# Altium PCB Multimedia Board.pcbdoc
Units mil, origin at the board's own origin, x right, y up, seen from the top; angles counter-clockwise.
Board outline 8820.47 x 865.35 mil, 4 copper layers (Top Layer, InternalPlane1, InternalPlane2, Bottom Layer); 37 components, 38 nets, 94 pads, 30 vias.
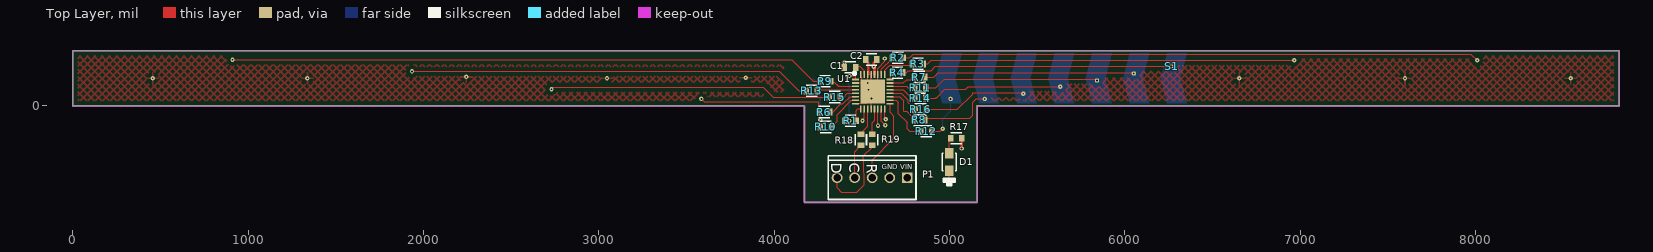
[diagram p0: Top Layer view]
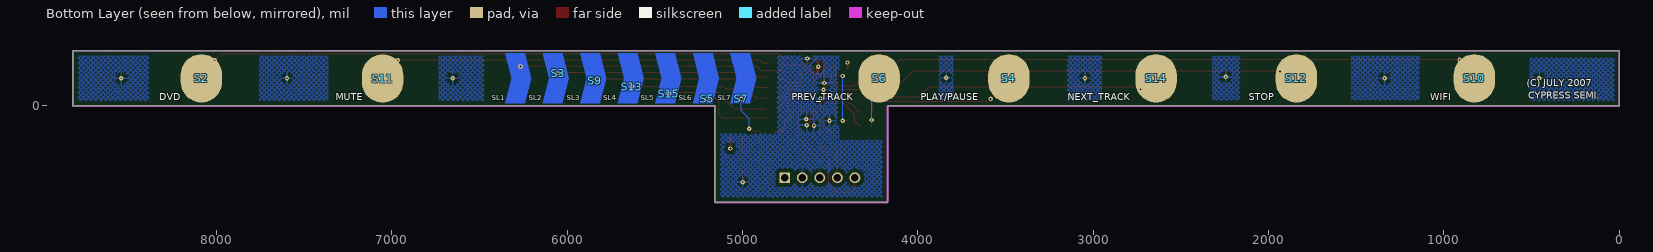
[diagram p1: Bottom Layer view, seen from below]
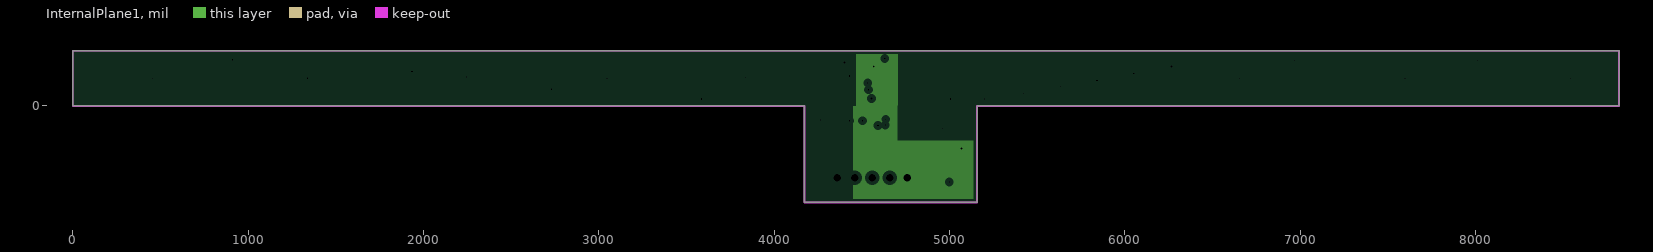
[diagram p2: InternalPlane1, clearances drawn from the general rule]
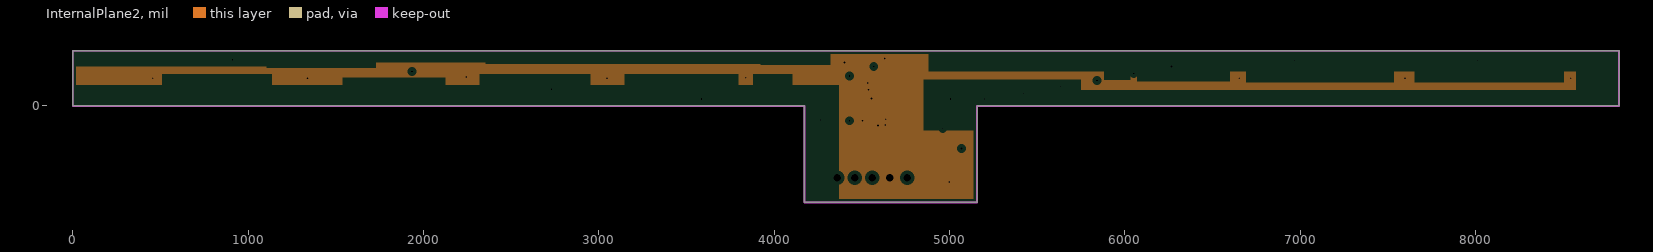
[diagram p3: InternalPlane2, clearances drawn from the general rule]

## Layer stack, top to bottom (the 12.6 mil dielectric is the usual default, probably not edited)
Top Layer: signal copper 1.4
Dielectric: prepreg 12.6, FR-4, Dk 4.8
InternalPlane1: plane copper 1.4, net VCC
Dielectric: prepreg 12.6, FR-4, Dk 4.8
InternalPlane2: plane copper 1.4, net GND
Dielectric: core 12.6, FR-4, Dk 4.8
Bottom Layer: signal copper 1.4

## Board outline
0,0 4172.05,0.39 4172.05,-550.39 5157.87,-550.39 5157.87,0.39 8820.47,0.39 8820.47,314.57 0,314.96

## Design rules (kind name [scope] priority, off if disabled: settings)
Clearance Clearance_1 [All vs InPoly] p1: gap=20
Clearance [All] p2: gap=7
ComponentClearance [All] p1 off: gap=10 collisioncheckmode=3 verticalgap=10
DiffPairsRouting [All] p1 off: maxlimit=10 minlimit=10 mostfreqgap=10 maxuncoupledlength=500
FanoutControl Fanout_BGA [IsBGA] p1 off: bgadir=Out bgaviamode=Centered fanoutstyle=Auto fanoutdirection=Alternating viagrid=1 // Fanout_BGA (Default Rule)
FanoutControl Fanout_LCC [IsLCC] p2 off: bgadir=Out bgaviamode=Centered fanoutstyle=Auto fanoutdirection=Alternating viagrid=1 // Fanout_LCC (Default Rule)
FanoutControl Fanout_SOIC [IsSOIC] p3 off: bgadir=Out bgaviamode=Centered fanoutstyle=Auto fanoutdirection=Alternating viagrid=1 // Fanout_SOIC (Default Rule)
FanoutControl Fanout_Small [(CompPinCount < 5)] p4 off: bgadir=Out bgaviamode=Centered fanoutstyle=Auto fanoutdirection=OutThenIn viagrid=1 // Fanout_Small (Default Rule)
FanoutControl Fanout_Default [All] p5 off: bgadir=Out bgaviamode=Centered fanoutstyle=Auto fanoutdirection=Alternating viagrid=1 // Fanout_Default (Default Rule)
HoleSize [All] p1: absolutevalues=TRUE maxlimit=150 minlimit=10 maxpercent=80.000 minpercent=20.000
MatchedLengths [InNetClass('ITO signals')] p1: tolerance=1000 amplitude=200 gap=20 style=Round
PlaneClearance [All] p1: clearance=20
PlaneConnect [All] p1: planeconnectstyle=Relief reliefexpansion=20 reliefentries=4 reliefconductorwidth=10 reliefairgap=10
PolygonConnect [All] p1: connectstyle=Relief reliefconductorwidth=10 reliefentries=4 polygonreliefangle="90 Angle"
RoutingTopology [All] p1 off: topology=Shortest
RoutingVias [All] p1: holewidth=10 width=25 viastyle="Through Hole" minholewidth=10 minwidth=25 maxholewidth=10 maxwidth=25
SMDNeckDown [All] p1 off: percent=80.000
SMDToPlane SMDToPlane_1 [InNet('VDD')] p1 off: distance=300000
SMDToPlane [InNet('GND')] p2 off: distance=300000
SolderMaskExpansion [All] p1: expansion=3
TestPointUsage [All] p1: valid=0 allowmultiple=FALSE
Testpoint [All] p1: side=15 testpointundercomponent=TRUE minsize=40 maxsize=100 preferedsize=60 minholesize=0 maxholesize=40 preferedholesize=32 testpointgrid=1 style=1023 order=0123456789
Width [All] p1: maxlimit=100 minlimit=7 preferedwidth=7 minimp=50.000000 maximp=50.000000 favimp=50.000000
8 further rules are at their usual default settings.

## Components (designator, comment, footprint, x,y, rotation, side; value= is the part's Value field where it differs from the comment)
C1 "0.1uF, 0603" 0603 4464.52,220 r180 top
C2 "0.1uF, 0603" 0603 4586.76,264.94 r180 top
D1 "LED" 0805LED 4999.52,-269.29 r270 top
P1 "ISSP_CON" ISPCON 4759.52,-409.29 r180 top
R1 "1K" 0603 4404.52,-84.29 r0 top
R2 "560 OHM" 0603 4736.76,274.94 r180 top
R3 "560 OHM" 0603 4851.76,239.94 r180 top
R4 "560 OHM" 0603 4734.75,189.94 r180 top
R6 "560 OHM" 0603 4316.76,-35.06 r180 top
R7 "560 OHM" 0603 4859.75,164.94 r180 top
R8 "560 OHM" 0603 4797.01,-80 r0 top
R9 "560 OHM" 0603 4259.52,140.71 r0 top
R10 "560 OHM" 0603 4326.76,-120.06 r180 top
R11 "560 OHM" 0603 4864.76,104.02 r180 top
R12 "560 OHM" 0603 4836.76,-145.06 r0 top
R13 "560 OHM" 0603 4184.52,85.71 r0 top
R14 "560 OHM" 0603 4864.75,44.94 r180 top
R15 "560 OHM" 0603 4314.52,50.71 r0 top
R16 "560 OHM" 0603 4866.76,-20.06 r180 top
R17 "330 OHM, 0603" 0603 5069.52,-184.29 r180 top
R18 "300 OHM" 0603 4495,-162.01 r270 top
R19 "300 OHM" 0603 4560,-162.01 r270 top
S1 "SL1" CAPSENSE_PAD 6266.85,225.04 r180 top
S2 "DVD" "BUTTON 9mm no silk"#1 7999.52,112.71 r180 top
S3 "SL2" CAPSENSE_PAD 6051.68,185.02 r0 bottom
S4 "PLAY/PAUSE" "BUTTON 9mm no silk"#2 3902.52,92.71 r180 top
S5 "SL6" CAPSENSE_PAD 5201.61,39.96 r0 bottom
S6 "PREV_TRACK" "BUTTON 9mm no silk"#3 4495.52,147.71 r180 top
S7 "SL7" CAPSENSE_PAD 5006.69,40.04 r0 bottom
S9 "SL3" CAPSENSE_PAD 5841.68,145.02 r0 bottom
S10 "WIFI" "BUTTON 9mm no silk"#4 2070.52,87.71 r180 top
S11 "MUTE" "BUTTON 9mm no silk"#5 7252.27,105.94 r180 top
S12 "STOP" "BUTTON 9mm no silk"#6 2556.52,92.71 r180 top
S13 "SL4" CAPSENSE_PAD 5631.69,110.04 r0 bottom
S14 "NEXT_TRACK" "BUTTON 9mm no silk"#7 3124.51,72.7 r180 top
S15 "SL5" CAPSENSE_PAD 5421.69,70.04 r0 bottom
U1 "CY8C21434-32PIN" 32-MLF 4464.52,150.71 r0 top

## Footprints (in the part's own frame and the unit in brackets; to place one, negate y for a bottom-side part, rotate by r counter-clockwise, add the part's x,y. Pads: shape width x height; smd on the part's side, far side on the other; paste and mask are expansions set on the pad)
32-MLF [mm]
  rect 3.5x3.5 smd: 0(2.5,-1.75)
  rect 1x0.23 smd: 1(0,0) 2(0,-0.5) 3(0,-1) 4(0,-1.5) 5(0,-2) 6(0,-2.5) 7(0,-3) 8(0,-3.5) 17(5,-3.5) 18(5,-3) 19(5,-2.5) 20(5,-2) 21(5,-1.5) 22(5,-1) 23(5,-0.5) 24(5,0)
  rect 0.23x1 smd: 9(0.75,-4.25) 10(1.25,-4.25) 11(1.75,-4.25) 12(2.25,-4.25) 13(2.75,-4.25) 14(3.25,-4.25) 15(3.75,-4.25) 16(4.25,-4.25) 25(4.25,0.75) 26(3.75,0.75) 27(3.25,0.75) 28(2.75,0.75) 29(2.25,0.75) 30(1.75,0.75) 31(1.25,0.75) 32(0.75,0.75)
  silkscreen extent -0.35,0.7 0.05,1.1
0603 [mm]
  rect 0.8x1 smd: 1(0,0) 2(1.6,0)
  silkscreen extent 0,-0.81 1.58,0.81
0805LED [mil]
  rect 60x50 smd: 1(0,0) 2(100,0)
  silkscreen extent 0,-40 187,40
"BUTTON 9mm no silk"#1 [mm]
  oval 6x7 smd far side: 1(-2.216,-1.137)
"BUTTON 9mm no silk"#2 [mm]
  oval 6x7 smd far side: 1(10.687,-1.645)
"BUTTON 9mm no silk"#3 [mm]
  oval 6x7 smd far side: 1(6.953,-0.248)
"BUTTON 9mm no silk"#4 [mm]
  oval 6x7 smd far side: 1(31.591,-1.772)
"BUTTON 9mm no silk"#5 [mm]
  oval 6x7 smd far side: 1(5.074,-1.264)
"BUTTON 9mm no silk"#6 [mm]
  oval 6x7 smd far side: 1(18.155,-1.645)
"BUTTON 9mm no silk"#7 [mm]
  oval 6x7 smd far side: 1(12.263,-2.152)
CAPSENSE_PAD [mil] "CAPSENSE_PAD"
  round 25 hole 10: 1(0.08,0.08)
ISPCON [mil]
  rect 62x62 hole 42: 1(0,0)
  round 62 hole 42: 2(100,0) 3(200,0) 4(300,0) 5(400,0)
  silkscreen extent -50,-125 450,125

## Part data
C1 C2: library part CAP, "Capacitor"
D1: "BLUE"
P1: "PSoC Programming Connector"
R1 R2 R3 R4 R6 R7 R8 R9 R10 R11 R12 R13 R14 R15 R16 R17 R18 R19: library part RES, "RESISTOR"
S1 S2 S3 S4 S5 S6 S7 S9 S10 S11 S12 S13 S14 S15: library part "CAPSENSE BUTTON"
U1: library part CY8C21434-24LFXI, "32  MLF"

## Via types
v1: diameter 25, hole 10, Top Layer to Bottom Layer, tented both sides, 16 vias
v2: diameter 25, hole 10, Top Layer to Bottom Layer, 14 vias

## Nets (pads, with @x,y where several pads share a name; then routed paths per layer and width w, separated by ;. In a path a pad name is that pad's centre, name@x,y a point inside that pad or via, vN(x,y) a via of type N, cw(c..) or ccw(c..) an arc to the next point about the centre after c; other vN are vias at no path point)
GND: C1.2 C2.2 D1.2 P1.2 U1.0 U1.2 U1.8 U1.10 U1.12 U1.14 U1.15 U1.16 U1.27 U1.29 U1.30 U1.32 | length 1127.4
  Top Layer w7: U1.8 4479.02,12.91 4481.82,15.71 4529.52,15.71 v2(4555.52,41.71) U1.12 ; U1.2 4534.21,131.02 v2(4534.52,130.71) ; U1.2@4479.41,131.02 U1.2@4479.72,130.71 ; U1.32 4494.05,165.74 4498.7,161.08 4498.7,131.52 v2(4538.52,91.71) ; v2(4504.52,-84.29) 4513.73,-75.08 U1.10 ; U1.30@4534.52,179.13 v2(4534.52,130.71) ; U1.30@4535.62,180.24 U1.29 4553.1,137.13 4546.68,130.71 v2(4534.52,130.71) ; U1.30@4536.53,191.14 4541.53,186.14 ; U1.0@4590.42,130.71 4592.47,132.76 4592.47,216.25 4594.44,216.25 4631.69,253.5 v2(4631.69,270.83) ; v2(4592.47,-112.24) U1.14 ; U1.15 4612.16,-86.93 v2(4634.52,-109.29) ; U1.16 4631.84,-71.61 v2(4636.52,-76.29) ; v2(4999.52,-434.29) D1.2
  Top Layer w10: C1.2@4401.53,210.71 v2(4401.53,247.72) ; 4541.53,186.14 4547.2,186.14
  Top Layer w15: U1.30@4536.53,191.14 C2.2@4536.53,245.71
  other v1: 456.69,157.48 1338.58,157.48 3047.24,157.48 6653.54,157.48 7598.43,157.48 8543.31,157.48 3838.58,161.42 2244.09,165.35
NetC1_1: C1.1 R1.1 U1.1 U1.31 | length 461.7
  Top Layer w7: R1.1 v2(4429.52,-84.29) ; v2(4429.52,170.71) 4464.52,170.71 ; U1.1 4464.52,210.71 4479.52,225.71 4489.52,225.71 4513.73,201.5 U1.31
  Bottom Layer w7: v2(4429.52,-84.29) v2(4429.52,170.71)
NetD1_1: D1.1 R17.2 | length 87.9
  Top Layer w7: D1.1 4999.52,-191.3 R17.2
NetR1_2: R1.2 U1.9 | length 88
  Top Layer w7: R1.2 4467.52,-27.29 4478.2,-16.61 U1.9
NetR2_1: R2.1 S2.1 | length 3296.4
  Top Layer w7: R2.1 4773.21,274.94 4793.48,295.21 7974.68,295.21 v1(8010.08,259.84)
NetR2_2: R2.2 U1.26 | length 120.2
  Top Layer w7: U1.26 4612.16,208.38 4673.76,269.98 R2.2
NetR3_1: R3.1 S11.1 | length 2134.4
  Top Layer w7: R3.1 4876.01,239.94 4895.89,259.83 v1(6966.77,259.84)
  Bottom Layer w7: v1(6966.77,259.84) S11.1@6974.63,251.95
NetR3_2: R3.2 U1.25 | length 190.8
  Top Layer w7: U1.25 4631.84,204.44 4659.67,232.27 4776.09,232.27 R3.2@4783.76,239.94
NetR4_1: R4.1 S1.1 | length 1546.5
  Top Layer w7: R4.1 4755.14,189.94 4765.97,200.77 4895.89,200.77 4920.06,224.94 S1.1@6266.76,224.94
NetR4_2: R4.2 U1.24 | length 50.6
  Top Layer w7: U1.24 4661.37,179.56 R4.2@4676.76,194.94
NetR6_1: R6.1 U1.6 | length 183.9
  Top Layer w7: R6.1 4333.29,-35.06 4380.06,11.71 4392.52,11.71 4433.09,52.28 U1.6
NetR6_2: R6.2 S4.1 | length 733.4
  Top Layer w7: v1(3585.63,40.12) 3602.14,23.61 4253.37,23.61 4253.76,23.21 R6.2
NetR7_1: R7.1 S3.1 | length 1203.6
  Top Layer w7: R7.1 4911.24,164.94 4935.26,188.96 6047.74,188.96 S3.1@6051.76,184.94
NetR7_2: R7.2 U1.23 | length 149.4
  Top Layer w7: U1.23 4737.29,131.02 4755.86,149.59 4781.4,149.59 R7.2
NetR8_1: R8.1 U1.19 | length 221.2
  Top Layer w7: U1.19 4717.95,52.28 4739.52,30.71 4739.52,-29.29 4755.99,-29.29 R8.1@4796.76,-70.06
NetR8_2: R8.2 S5.1 | length 430.3
  Top Layer w7: R8.2@4859.75,-70.06 5115.54,-70.06 5132.11,-53.48 5132.11,19.67 5152.31,39.87 S5.1
NetR9_1: R9.1 S10.1 | length 3398.9
  Top Layer w7: v1@911.64,263.76 4100.61,263.76 4223.67,140.71 R9.1
  other v1: 911.65,263.78
NetR9_2: R9.2 U1.3 | length 147.1
  Top Layer w7: R9.2@4327.51,135.71 4342.51,135.71 4366.88,111.34 U1.3
NetR10_1: R10.1 U1.7 | length 223.3
  Top Layer w7: R10.1 4359.52,-87.29 4359.52,-49.29 4441.41,32.6 U1.7
NetR10_2: R10.2 S6.1 | length 294.9
  Top Layer w7: R10.2 v1(4263.78,-80.47)
  Bottom Layer w7: S6.1 4262.03,117.19 4262.03,-78.76 v1(4263.78,-80.47)
NetR11_1: R11.1 S9.1 | length 1005.7
  Top Layer w7: R11.1@4859.75,104.94 4922.11,104.94 4970.69,153.53 5833.17,153.53 S9.1@5841.76,144.94
NetR11_2: R11.2 U1.22 | length 138
  Top Layer w7: U1.22 4756.98,111.34 4763.37,104.94 R11.2@4796.76,104.94
NetR12_1: R12.1 U1.18 | length 308.8
  Top Layer w7: U1.18 4697.63,32.6 4709.52,20.71 4709.52,-44.29 4759.52,-94.29 4759.52,-131.36 4773.21,-145.06 R12.1
NetR12_2: R12.2 S7.1 | length 256.7
  Top Layer w7: R12.2 4946.44,-145.06 v1(4961.57,-129.92)
  Bottom Layer w7: v1(4961.57,-129.92) 4961.56,-72.14 5006.76,-26.95 S7.1@5006.76,39.94
NetR13_1: R13.1 S12.1 | length 2295.3
  Top Layer w7: v1@1935.26,196.83 4029.75,196.83 4140.87,85.71 R13.1
  other v1: 1935.28,196.85
NetR13_2: R13.2 U1.4 | length 212.4
  Top Layer w7: R13.2@4252.51,90.71 4253.46,91.65 U1.4
NetR14_1: R14.1 S13.1 | length 796.6
  Top Layer w7: R14.1 4925.73,44.94 4925.73,49.51 4929.67,49.51 4974.63,94.47 5092.74,94.47 5108.21,109.94 S13.1@5631.76,109.94
NetR14_2: R14.2 U1.21 | length 160.5
  Top Layer w7: U1.21 4738.58,91.65 4738.58,90.37 4784,44.94 R14.2
NetR15_1: R15.1 S14.1 | length 1607
  Top Layer w7: v1@2730.54,106.28 3939.2,106.28 3994.77,50.71 R15.1
  other v1: 2730.55,94.49
NetR15_2: R15.2 U1.5 | length 95.8
  Top Layer w7: R15.2 4397.52,50.71 4418.78,71.97 U1.5
NetR16_1: R16.1 S15.1 | length 603.3
  Top Layer w7: R16.1 5045.14,-20.06 5132.11,66.91 5132.11,74.79 5416.91,74.79 S15.1@5423.45,68.25
NetR16_2: R16.2 U1.20 | length 190.2
  Top Layer w7: U1.20 4728.26,71.97 4728.26,69.19 4765.97,31.48 4765.97,17.74 R16.2
NetR18_1: R18.1 U1.11 | length 161.3
  Top Layer w7: R18.1 4495,-155 4533.42,-116.58 U1.11
NetR19_1: R19.1 U1.13 | length 150.7
  Top Layer w7: R19.1 4560,-95 4572.79,-82.21 U1.13
SCL: P1.4 R18.2 | length 198.8
  Top Layer w7: P1.4 4460,-280 4460,-260 R18.2
SDA: P1.5 R19.2 | length 483.8
  Top Layer w7: P1.5 4359.52,-467.58 4384.08,-492.14 4470.69,-492.14 4510.06,-452.77 4510,-310 4510,-285 4560,-235 R19.2
VCC: C2.1 P1.1 R17.1 U1.28 | length 144.9
  Top Layer w10: C2.1 C2.1@4586.76,269.94
  Top Layer w15: v2(4569.12,224.39) 4569.12,247.31 C2.1 ; U1.28 v2@4572.79,213.98 ; v2(5069.49,-242.56) R17.1
XRES: P1.3 U1.17 | length 482.6
  Top Layer w7: P1.3 4559.52,-308.83 4683.29,-185.06 4683.29,-59.07 4661.37,-37.15 U1.17

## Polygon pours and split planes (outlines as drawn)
GND on Top Layer "Top Layer-GND 1" (hatched 45Degree grid 30 track 8, remove dead copper, pour order 1001): -85,380 -95,370 -95,-110 4150,-110 4155,-105 4055,-5 4055,470 0,470 -95,375 -95,370
GND on Top Layer "Top Layer-GND" (hatched 45Degree grid 30 track 8, remove dead copper, pour order 1000): 6480,-185 5235,-185 5185,-135 5155,-105 5155,410 9260,410 9285,385 9315,355 9315,-185
GND on Bottom Layer "Bottom Layer-GND 8" (hatched 45Degree grid 20 track 7.99, remove dead copper, pour order 1010): 8385.83,295.28 8385.83,19.68 8799.21,19.68 8799.21,295.28
GND on Bottom Layer "Bottom Layer-GND 7" (hatched 45Degree grid 20 track 7.99, remove dead copper, pour order 1009): 7362.2,295.28 7362.2,19.68 7755.91,19.68 7755.91,295.28 7362.2,295.28
GND on Bottom Layer "Bottom Layer-GND 6" (hatched 45Degree grid 20 track 7.99, pour order 1008): 6476.38,295.28 6476.38,19.68 6732.28,19.68 6732.28,295.28 6476.38,295.28
GND on Bottom Layer "Bottom Layer-GND 5" (hatched 45Degree grid 20 track 7.99, remove dead copper, pour order 1007): 511.81,275.59 511.81,23.62 15.75,23.62 15.75,275.59
GND on Bottom Layer "Bottom Layer-GND 4" (hatched 45Degree grid 20 track 7.99, remove dead copper, pour order 1006): 1141.73,283.46 1527.56,283.46 1527.56,31.5 1141.73,31.5
GND on Bottom Layer "Bottom Layer-GND 3" (hatched 45Degree grid 20 track 7.99, remove dead copper, pour order 1005): 2165.35,283.46 2322.83,283.46 2322.83,31.5 2165.35,31.5
GND on Bottom Layer "Bottom Layer-GND 2" (hatched 45Degree grid 20 track 7.99, pour order 1004): 2952.76,291.34 3149.61,291.34 3149.61,23.62 2952.76,23.62
GND on Bottom Layer "Bottom Layer-GND 1" (hatched 45Degree grid 20 track 7.99, remove dead copper, pour order 1003): 3799.21,428.41 3799.21,-99.15 3877.95,-99.15 3877.95,428.41
GND on Bottom Layer "Bottom Layer-GND" (hatched 45Degree grid 20 track 8, remove dead copper, pour order 1002): 4803.15,314.96 4803.15,-157.48 5275.59,-157.48 5275.59,-629.92 4015.75,-629.92 4015.75,-196.85 4448.82,-196.85 4448.82,314.96
VCC on InternalPlane1 (split plane): 4709.53,294.36 4709.53,0 4704.72,0 4704.72,-196.85 5137.48,-196.85 5137.48,-530 4448.82,-530 4448.82,0 4464.53,0 4464.53,294.37
GND on InternalPlane2 (split plane): 8800.08,294.18 8800.08,196.85 8574.8,196.85 8574.8,90 5750,90 5750,150 4854.72,150 4854.72,67.01 4855,67.01 4855,-140 5137.48,-140 5137.48,-530 4192.44,-530 4192.44,0.39 4192.44,0.4 4191.72,3.99 4190.89,8.2 4188.83,11.27 4186.47,14.81 4183.29,16.94 4179.85,19.23 4176.14,19.97 4172.05,20.79 20.39,20.39 20.39,225 1130,225 1130,250 2355,250 2355,240 3163.61,240 3163.61,239.79 3925,239.79 3925,235 4320,235 4320,294.38

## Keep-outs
Keep-Out Layer:
  lines w10: 0,0 0,314.96 8818.9,314.96 8818.9,0 5157.48,0 5157.48,-551.18 4173.23,-551.18 4173.23,0 0,0

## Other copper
Top Layer:
  region: 4374.52,111.34 4342.51,135.71
  region: 4553.1,-16.61 4555.52,41.71
  text "TOP COPPER (.GTL)" at 925,3650 h40
  text "life-support systems where a malfunction or failure may reasonably be" at 4250,2425 h60
  text "expected to result in significant injury to the user. The inclusion of" at 4250,2275 h60
  text "Cypress. product in a life-support systems application implies that the" at 4250,2150 h60
  text "manufacturer assumes all risk of such use and in doing so indemnifies" at 4250,2025 h60
  text "Cypress against all charges." at 4250,1900 h60
  text "Use of this software may be limited by and subject to the applicable" at 4250,1775 h60
  text "Cypress software license agreement." at 4250,1650 h60
Bottom Layer:
  region: 4414.52,155.71 4374.52,155.71 4414.52,155.71
  region net NetR4_1: 6242.42,299.94 6205.88,157.82 6242.42,14.94 6353.52,14.94 6316.98,157.82 6353.76,299.94
  region net NetR7_1: 6028.42,300.94 5991.88,158.82 6028.42,15.94 6139.52,15.94 6102.98,158.82 6139.76,300.94
  region net NetR11_1: 5814.42,300.94 5777.88,158.82 5814.42,15.94 5925.52,15.94 5888.98,158.82 5925.76,300.94
  region net NetR14_1: 5600.42,300.94 5563.88,158.82 5600.42,15.94 5711.52,15.94 5674.98,158.82 5711.76,300.94
  region net NetR16_1: 5386.42,300.94 5349.88,158.82 5386.42,15.94 5497.52,15.94 5460.98,158.82 5497.76,300.94
  region net NetR8_2: 5171.42,300.94 5134.88,158.82 5171.42,15.94 5282.52,15.94 5245.98,158.82 5282.76,300.94
  region net NetR12_2: 4958.42,300.94 4921.88,158.82 4958.42,15.94 5069.52,15.94 5032.98,158.82 5069.76,300.94
  text "BOTTOM COPPER (.GBL)" at 925,3200 h40
InternalPlane1 (plane layer: these items are gaps in the copper):
  rectangle: 4173.23,-551.18 4448.82,0
  rectangle: 4709.53,0 8818.9,314.96
  rectangle: 0,0 4464.53,314.96
  rectangle: 4704.72,-196.85 5157.48,0
  text "INTERNAL PLANE 1 (.GP1)" at 925,3500 h40
InternalPlane2 (plane layer: these items are gaps in the copper):
  rectangle: 8574.8,90 8803.15,196.85
  rectangle: 7653.54,133.86 8503.94,196.85
  rectangle: 6692.91,133.86 7535.43,196.85
  rectangle: 6070.87,141.73 6598.43,196.85
  rectangle: 5881.89,149.61 6031.5,196.85
  rectangle: 4854.72,67.01 5750,150
  rectangle: 3881.89,118.11 4102.36,181.1
  rectangle: 3149.61,118.11 3795.28,181.1
  rectangle: 1540,85 2125,160
  rectangle: 0,225 1130,300
  rectangle: 2355,240 3230,315
  rectangle: 3163.61,239.79 3945,314.79
  rectangle: 3925,235 4320,310
  rectangle: 6410,10 8805,90
  rectangle: 4855,-140 5157.87,80
  rectangle: 5140,10 6435,90
  rectangle: 1110,250 2380,305
  rectangle: 3935,240 3945,255
  region: 2322.83,125.98 2322.83,181.1 2952.76,181.1 2952.76,118.11 2322.83,118.11
  region: 511.81,118.11 1133.86,118.11 1133.86,181.1 511.81,181.1
  region: 4881.89,314.96 4881.89,196.85 8818.9,196.85 8818.9,314.96
  region: 0,118.11 0,0 4173.23,0 4173.23,-551.18 4370.08,-551.18 4370.08,118.11
  region: 1106.81,218.11 1728.86,218.11 1728.86,281.1 1106.81,281.1
  text "INTERNAL PLANE 2 (.GP2)" at 925,3350 h40

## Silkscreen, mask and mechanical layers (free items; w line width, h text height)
Top Overlay:
  text "TOP OVERLAY (.GTO)" at 925,3900 h40
Bottom Overlay:
  text "BOTTOM SILKSCREEN (.GBO)" at 925,3050 h40
  text "(C) JULY 2007" at 526.77,111.02 h40
  text "CYPRESS SEMI." at 518.11,42.13 h40
Top Paste:
  text "TOP PASTE (.GTP)" at 2775,3250 h40
Bottom Paste:
  lines w10: 0,0 4173.23,0 4173.23,-551.18 5157.48,-551.18 5157.48,0 8818.9,0 8818.9,314.96 0,314.96 0,0
  text "BOTTOM PASTE (.GBP)" at 2775,3100 h40
Top Solder:
  text "TOP SOLDERMASK (.GTS)" at 925,3775 h40
Bottom Solder:
  text "BOTTOM SOLDERMASK (.GBS)" at 925,2900 h40
Mechanical 1:
  lines w10: 0,0 0,314.96 8818.9,314.96 8818.9,0 5157.48,0 5157.48,-551.18 4173.23,-551.18 4173.23,0 0,0
Drill Drawing:
  lines w10: 4250.29,5573.51 4250.29,6673.51 cw(c4350.29,6673.51) 4350.29,6773.51 9900.29,6773.51 cw(c9900.29,6673.51) 10000.29,6673.51 10000.29,5573.51 cw(c9900.29,5573.51) 9900.29,5473.51 4349.53,5473.53 cw(c4351.29,5574.51) 4250.29,5574.51 ; 4725.29,5623.51 4825.29,5623.51 ; 5325.29,5623.51 5425.29,5623.51 ; 5550.29,5723.51 4350.29,5723.51 ccw(c4350.29,5673.51) 4300.29,5673.51 4300.29,5573.51 ccw(c4350.29,5573.51) 4350.29,5523.51 5550.29,5525.51 ccw(c5550.29,5573.51) 5598.29,5573.51 ; 5550.29,5773.51 4350.29,5773.51 cw(c4350.29,5823.51) 4300.29,5823.51 4300.29,6673.51 cw(c4350.29,6673.51) 4350.29,6723.51 5550.29,6723.51 ; 5550.29,5775.51 ccw(c5550.29,5823.51) 5598.29,5823.51 ; 5551.29,5723.51 cw(c5551.29,5674.51) 5600.29,5674.51 ; 5551.29,6723.51 cw(c5551.29,6674.51) 5600.29,6674.51 ; 5600.29,5573.51 5600.29,5673.51 ; 5600.29,5823.51 5600.29,6673.51 ; 5699.42,5523.52 cw(c5700.29,5573.51) 5650.29,5573.51 5650.29,5673.51 cw(c5700.29,5673.51) 5700.29,5723.51 7375.29,5723.51 cw(c7375.29,5673.51) 7425.29,5673.51 7425.29,5573.51 ; 5699.42,5773.52 cw(c5700.29,5823.51) 5650.29,5823.51 5650.29,6048.51 cw(c5700.29,6048.51) 5700.29,6098.51 6450.29,6098.51 ; 5700.29,5523.51 7375.29,5523.51 ; 5700.29,5773.51 6450.29,5773.51 ; 6449.58,6098.48 cw(c6451.29,6049.51) 6500.29,6049.51 ; 6450.29,6148.51 5700.29,6148.51 cw(c5700.29,6198.51) 5650.29,6198.51 5650.29,6423.51 cw(c5700.29,6423.51) 5700.29,6473.51 6450.29,6473.51 ; 6451.29,5773.51 ccw(c6451.29,5822.51) 6500.29,5822.51 ; 6451.29,6473.51 cw(c6451.29,6424.51) 6500.29,6424.51 ; 6452.29,6148.51 ccw(c6452.29,6196.51) 6500.29,6196.51 ; 6500.29,5823.51 6500.29,6048.51 ; 6500.29,6198.51 6500.29,6423.51 ; 6550.29,5822.51 ccw(c6599.29,5822.51) 6599.29,5773.51 8201.29,5773.51 ccw(c8201.29,5822.51) 8250.28,5823.37 ; 6550.29,5823.51 6550.29,5948.51 cw(c6600.29,5948.51) 6600.29,5998.51 8200.29,5998.51 ; 6550.29,6097.51 ccw(c6599.29,6097.51) 6599.29,6048.51 ; 6550.29,6098.51 6550.29,6423.51 cw(c6600.29,6423.51) 6600.29,6473.51 8650.29,6473.51 cw(c8650.29,6423.51) 8700.29,6423.51 8700.29,6098.51 cw(c8650.29,6098.51) 8651.16,6048.51 ; 6600.29,6048.51 8650.29,6048.51 ; 7376.45,5523.51 ccw(c7377.29,5571.51) 7425.27,5573.19 ; 7524.42,5523.52 cw(c7525.29,5573.51) 7475.29,5573.51 7475.29,5673.51 cw(c7525.29,5673.51) 7525.29,5723.51 9200.29,5723.51 cw(c9200.29,5673.51) 9250.29,5673.51 9250.29,5573.51 ; 7525.29,5523.51 9200.29,5523.51 ; 8201.29,5998.51 cw(c8201.29,5949.51) 8250.29,5949.51 ; 8250.29,5823.51 8250.29,5948.51 ; 8300.29,5823.51 8300.29,5948.51 ; 8300.29,5824.51 ccw(c8351.29,5824.51) 8350.4,5773.52 ; 8300.36,5948 cw(c8348.29,5950.51) 8348.29,5998.51 ; 8350.29,5773.51 8650.29,5773.51 ccw(c8650.29,5823.51) 8700.29,5823.51 8700.29,5948.51 ; 8350.29,5998.51 8650.29,5998.51 ; 8651.29,5998.51 cw(c8651.29,5949.51) 8700.29,5949.51 ; 8750.29,5822.51 ccw(c8799.29,5822.51) 8800.15,5773.52 ; 8750.29,5823.51 8750.29,5948.51 cw(c8800.29,5948.51) 8800.29,5998.51 9900.29,5998.51 ; 8800.29,5773.51 9900.29,5773.51 ccw(c9900.29,5823.51) 9950.29,5823.51 9950.29,5949.51 ccw(c9901.29,5949.51) 9901.29,5998.51 ; 9201.45,5523.51 ccw(c9202.29,5571.51) 9250.27,5573.19 ; 9300.29,5572.51 ccw(c9349.29,5572.51) 9350.15,5523.52 ; 9300.29,5573.51 9300.29,5673.51 cw(c9350.29,5673.51) 9350.29,5723.51 9900.29,5723.51 cw(c9900.29,5673.51) 9950.29,5674.38 ; 9350.29,5523.51 9900.29,5523.51 ccw(c9900.29,5573.51) 9950.29,5573.51 9950.29,5673.51 ; 9899.58,6723.48 cw(c9901.29,6674.51) 9950.29,6674.51 ; 9900.29,6723.51 8800.29,6723.51 ccw(c8800.29,6673.51) 8750.29,6673.51 8750.29,6098.51 ccw(c8800.29,6098.51) 8800.29,6048.51 9900.29,6048.51 ccw(c9900.29,6098.51) 9950.29,6098.51 9950.29,6673.51 ; 0,0 0,314.96 8818.9,314.96 8818.9,0 5157.48,0 5157.48,-551.18 4173.23,-551.18 4173.23,0 0,0 ; 5650.29,6573.51 ccw(c5700.29,6573.51) 5700.29,6523.51 8650.29,6523.51 ccw(c8650.29,6573.51) 8700.29,6573.51 8700.29,6673.51 ccw(c8650.29,6673.51) 8650.29,6723.51 5700.29,6723.51 ccw(c5700.29,6673.51) 5650.29,6673.51 5650.29,6573.51
  text "NOTES:" at 4805.71,7705.51 h40
  text "LAYER STACK:" at 7215.71,7695.51 h40
  text "1. MATERIAL: 4 LAYERS, FR4,  0.062\" +/-10% IN. THK." at 4805.71,7587.4 h40
  text "LAYER 1  .GTL" at 7215.71,7577.4 h40
  text ".LEGEND" at 10152.17,7571.65 h40
  text "2. 1 OZ. COPPER THICKNESS." at 4805.71,7469.29 h40
  text "LAYER2   .GP1" at 7215.71,7459.29 h40
  text "3. SOLDERMASK: TWO SIDES, LPI." at 4805.71,7351.18 h40
  text "LAYER3   .GP2" at 7215.71,7341.18 h40
  text "4. HOLE SIZES: FINISHED SIZES LISTED." at 4805.71,7233.07 h40
  text "LAYER4   .GBL" at 7215.71,7223.07 h40
  text "5. MINIMUM SPACE .007'', MINIMUM TRACE .007''." at 4805.71,7114.96 h40
  text "6. SILKSCREEN: 2 SIDES,  WHITE EPOXY INK." at 4805.71,6996.85 h40
  text "Cypress Semiconductor" at 6359.29,6595.51 h40
  text "CYPRESS SEMICONDUCTOR" at 8789.29,6579.84 h40
  text "DIMs AS NOTED" at 4450.91,6518.07 h40
  text "2700-162ND ST SW" at 8915.29,6443.51 h40
  text "TITLE:" at 6587.79,6386.01 h40
  text "ENGR:" at 5700.29,6373.51 h40
  text "LYNNWOOD, WA 98087" at 8845.29,6333.51 h40
  text "GABRIEL ROWE" at 5794.29,6280.51 h40
  text "USA" at 9235.29,6233.51 h40
  text "CAPSENSE IHR" at 6889.29,6229.84 h40
  text "(425) 787-4896" at 5739.29,6179.84 h40
  text "CAD:" at 5675.29,5993.51 h40
  text "GABRIEL ROWE" at 5865.28,5993.5 h40
  text "PART NO.:" at 6600.29,5911.01 h40
  text "REV:" at 8337.79,5911.01 h40
  text "DATE:" at 8800.29,5911.01 h40
  text "(425) 787-4896" at 5750.28,5843.5 h40
  text "24 JULY 2007" at 8980.28,5828.5 h40
  text "A" at 8514.29,5804.84 h40
  text "MATERIAL" at 4350.29,5648.51 h40
  text "FILE NAME:" at 5700.29,5633.51 h40
  text "LAYER:" at 7540.29,5633.51 h40
  text "GERBER:" at 9360.29,5633.51 h40
  text "SEE NOTES" at 4875.29,5598.51 h40
  text "CAPSENSE_IHR" at 6089.29,5579.84 h40
  text "Copyright 2008 Cypress Semiconductor Corporation." at 4275,5175 h60
  text "This software is owned by Cypress Semiconductor Corporation (Cypress)" at 4250,4950 h60
  text "and is protected by and subject to worldwide patent protection (United" at 4250,4800 h60
  text "States and foreign), United States copyright laws and international treaty" at 4250,4650 h60
  text "provisions. Therefore, unless otherwise specified in a separate license" at 4250,4500 h60
  text "agreement between you and Cypress, this software must be treated like" at 4250,4325 h60
  text "any other copyrighted material. Reproduction, modification, translation," at 4250,4175 h60
  text "DRILL AND TRIM(.GD1)" at 925,4075 h40
  text "compilation, or representation of this software in any other form (e.g.," at 4250,4025 h60
  text "paper, magnetic, optical, silicon, etc.) is prohibited without Cypress." at 4250,3875 h60
  text "express written permission." at 4250,3725 h60
  text "Disclaimer: CYPRESS MAKES NO WARRANTY OF ANY KIND," at 4250,3500 h60
  text "EXPRESS OR IMPLIED, WITH REGARD TO THIS MATERIAL," at 4250,3375 h60
  text "INCLUDING, BUT NOT LIMITED TO, THE IMPLIED WARRANTIES OF" at 4250,3250 h60
  text "MERCHANTABILITY AND FITNESS FOR A PARTICULAR PURPOSE." at 4250,3125 h60
  text "Cypress reserves the right to make changes without further notice to the" at 4250,3000 h60
  text "materials described herein. Cypress does not assume any liability arising" at 4250,2875 h60
  text "out of the application or use of any product or circuit described herein." at 4250,2750 h60
  text "Cypress does not authorize its products for use as critical components in" at 4250,2600 h60

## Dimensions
4359.52,-409.29 to 4173.23,-551.18 on Drill Drawing
4359.52,-409.29 to 4173.23,-551.18 on Drill Drawing
5157.48,0 to 5157.48,-551.18 on Drill Drawing
0,314.96 to 0,0 on Drill Drawing
0,314.96 to 8818.9,314.96 on Drill Drawing
4173.23,0 to 5157.48,-551.18 on Drill Drawing
0,0 to 4172.05,-550.39 on Drill Drawing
